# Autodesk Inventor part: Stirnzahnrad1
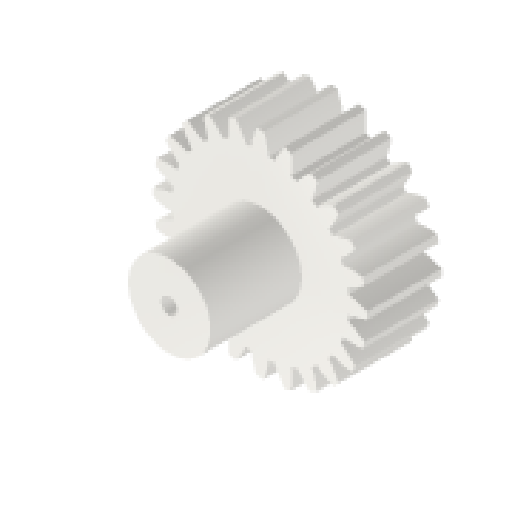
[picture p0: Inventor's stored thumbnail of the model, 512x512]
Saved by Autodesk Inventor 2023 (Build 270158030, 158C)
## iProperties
CustomPartVersion: 1
Created: 2022-09
Part Number: Stirnzahnrad1
Material: Steel
Document SubType Name: Modeling
Designer: Christoph Steinmann
Categories: <?xml version="1.0" encoding="UTF-16"?> <MemberInstance><Categories><FamilyTemplate><FamilyTemplateParameter ValueType="xs:double" Id="1" ObjectReferenceKey="da
Density: 1 g/cm^3
Appearance: Steel
Author: Christoph Steinmann
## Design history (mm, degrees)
sketch "Sketch1"
  geometry: C1 r 26 at (0, 0)
  constraints: 1 centre point
  dimensions: "d0" = 52 diameter of C1 (= da_da)
extrude "Extrusion1" new body sketch "Sketch1" distance "d1" = 20 (= da_b); taper "d2" = 0 deg
workplane "Work Plane2"
sketch "Sketch2"
  geometry: C1 r 26 at (0, 0) reference; C2 r 24 at (0, 0)
  constraints: 1 centre point, 1 coincident
  dimensions: "d3" = 48 diameter of C2 (= da_d)
feature "Flankendurchmesser" sketch "Sketch2" dims "d4" = 10, "d5" = 0
workplane "Work Plane8"
workplane "Work Plane9"
feature "Stirnzahnrad" dims "da_b" = 20, "da_d" = 48, "da_aw" = 60, "da_da" = 52, "da_df" = 43, "da_dw" = 48, angle "da_beta" = 0 deg, "da_lefttooth" = 0, "da_righttooth" = 0
sketch "Skizze3"
  geometry: C1 r 10 at (0, 0); 1 further point
  constraints: 1 centre point, 1 coincident
  dimensions: "d49" = 20 diameter of C1
extrude "Extrusion2" join sketch "Skizze3" distance "d50" = 22; taper "d51" = 0 deg
sketch "Skizze4"
  geometry: C1 r 26 at (0, 0); C2 r 10 at (0, 0) reference; A1 r 26 centre (0, 0) between (-13.73, -22.079) and (-12.256, -22.93) reference; 1 further point
  constraints: 1 centre point, 1 coincident, 1 concentric
extrude "Extrusion3" cut sketch "Skizze4" distance "d52" = 2; taper "d53" = 0 deg
sketch "Skizze5"
  geometry: C1 r 2 at (0, 0); 1 further point
  constraints: 1 centre point, 1 coincident
  dimensions: "d54" = 4 diameter of C1
extrude "Extrusion4" cut sketch "Skizze5" extent not by distance; stored distance "d55" = 0; taper "d56" = 0 deg
body "Solid1"
body "Srf1"
other parameters: "d17" = 0, "d34" = 7.5 deg (computed from da_z), "d39" = 0, "d41" = 0, "d47" = 0, "d48" = 0
